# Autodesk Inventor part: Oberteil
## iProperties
Created: 2007-04
Part Number: Oberteil
Document SubType Name: Sheet Metal
Designer: Benno
Manufacturer: Standard
Standards Organization: Custom
Author: Benno
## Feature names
1. Extrusion1
2. Bohrung1 [Hole]
3. Extrusion2
4. Grobblech1
5. Grobblech2
6. Biegung1
7. Grobblech3
8. Biegung2
9. ExtrusionAbwicklung1
